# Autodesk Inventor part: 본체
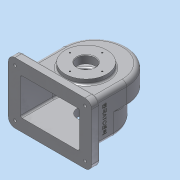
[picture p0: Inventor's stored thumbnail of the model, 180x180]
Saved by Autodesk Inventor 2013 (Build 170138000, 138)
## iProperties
Created: 2017-11
Part Number: 본체
Material: 알루미늄 6061
Document SubType Name: Modeling
Designer: dgall
Density: 2.71 g/cm^3
Mass: 1079.49 g
Surface Area: 1182.07 cm^2
Volume: 398.335 cm^3
Author: dgall
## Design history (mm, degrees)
sketch "스케치3"
  geometry: L1 (-58, 0)-(-58, -80); L2 (-58, -80)-(58, -80); L3 (58, -80)-(58, 0); A1 r 58 centre (0, 0) between (58, 0) and (-58, 0); 1 further point
  constraints: 6 end point, 2 point on circle, 2 tangent, 1 centre point, 1 coincident, 1 horizontal alignment, 1 perpendicular, 1 vertical
  dimensions: "d8" = 58 radius of A1; "d9" = 80 distance of L1.start L1.end
extrude "돌출2" new body sketch "스케치3" stored distance "d10" = 38; taper "d11" = 0 deg
sketch "스케치4"
  geometry: L1 (-58, 0)-(-58, -80) reference; L2 (-58, -80)-(58, -80) reference; L3 (58, -80)-(58, 0) reference; L4 (-58, -23)-(-58, -80); L5 (58, -80)-(-58, -80); L6 (58, -80)-(58, -23); A1 r 58 centre (0, 0) between (58, 0) and (-58, 0) reference; A2 r 58 centre (0, -23) between (58, -23) and (-58, -23)
  constraints: 6 end point, 2 collinear, 2 point on circle, 2 point on line, 1 centre point, 1 vertical alignment
  dimensions: "d12" = 58 radius of A2; "d13" = 57 distance from line of A2.centre L2
extrude "돌출3" join sketch "스케치4" distance "d14" = 38; taper "d15" = 0 deg
feature "쉘1" dims "d16" = 5
sketch "스케치5"
  geometry: L1 (5, -71)-(5, -5) reference; L2 (116, 0)-(116, -76) reference; L3 (0, 0)-(116, 0) reference; L4 (0, 0)-(0, -76) reference; L5 (116, -76)-(0, -76) reference; L6 (-17, 17)-(133, 17); L7 (133, 17)-(133, -93); L8 (133, -93)-(-17, -93); L9 (-17, -93)-(-17, 17); 4 further points
  constraints: 8 end point, 3 midpoint, 2 parallel, 1 horizontal, 1 horizontal alignment, 1 perpendicular, 1 vertical alignment
  dimensions: "d17" = 110 distance of L8.end L6.start; "d19" = 150 distance of L7.end L8.end
extrude "돌출4" join sketch "스케치5" distance "d20" = 15; taper "d21" = 0 deg
node "작업 평면3"
sketch "스케치6"
  geometry: C1 r 6 at (-75, -36); 1 further point
  constraints: 1 centre point, 1 coincident
  dimensions: "d24" = 12 diameter of C1
extrude "돌출5" join sketch "스케치6" stored distance "d25" = 15; taper "d26" = 0 deg
sketch "스케치7"
  geometry: C1 r 6 at (0, 0) reference; 1 further point
  constraints: 1 coincident
hole "구멍1" sketch "스케치7" at (0, 0) diameter "d27" = 4.459; stored, may be unused: countersink angle "d31" = 90 deg, drill point angle "d33" = 118 deg; dims "d28" = 6, "d29" = 4, "d30" = 2, "d32" = 8
sketch "스케치8"
  geometry: L1 (-75, -80)-(75, -80) reference; C1 r 37.5 at (0, -15); A1 r 58 centre (0, 0) between (58, 0) and (-58, 0) reference
  constraints: 1 centre point, 1 vertical alignment
  dimensions: "d34" = 75 diameter of C1; "d35" = 65 distance from line of C1.centre L1
extrude "돌출6" join sketch "스케치8" distance "d36" = 9; taper "d37" = 0 deg
sketch "스케치9"
  geometry: L1 (-75, -80)-(75, -80) reference; C1 r 31 at (0, -15); 1 further point
  constraints: 1 centre point, 1 vertical alignment
  dimensions: "d41" = 62 diameter of C1; "d42" = 65 distance from line of L1 C1.centre
extrude "돌출7" join sketch "스케치9" distance "d43" = 10; taper "d44" = 0 deg
sketch "스케치10"
  geometry: C1 r 31 at (0, 0) reference; 2 further points
  constraints: 1 coincident
hole "구멍2" sketch "스케치10" at (0, 0) diameter "d45" = 32; stored, may be unused: countersink angle "d49" = 90 deg, drill point angle "d51" = 118 deg; dims "d46" = 6, "d47" = 4, "d48" = 2, "d50" = 8
sketch "스케치11" dims "d52" = 52
  geometry: C1 r 31 at (0, 0) reference; 3 further points
  constraints: 2 vertical alignment, 1 coincident, 2 other
hole "구멍3" sketch "스케치11" at (0, 26) diameter "d53" = 2.459; stored, may be unused: countersink angle "d57" = 90 deg, drill point angle "d59" = 118 deg; dims "d54" = 6, "d55" = 4, "d56" = 2, "d58" = 8
sketch "스케치12" dims "d63" = 58
  geometry: C1 r 37.5 at (0, 0) reference; 3 further points
  constraints: 2 vertical alignment, 1 coincident, 2 other
hole "구멍4" sketch "스케치12" at (0, 29) diameter "d64" = 2.459; stored, may be unused: countersink angle "d68" = 90 deg, drill point angle "d70" = 118 deg; dims "d65" = 6, "d66" = 4, "d67" = 2, "d69" = 8
fillet "모깎기1" dims "d74" = 12
sketch "스케치13"
  geometry: A1 r 12 centre (-5, 81) between (-5, 93) and (-17, 81) reference; A2 r 12 centre (-5, -5) between (-17, -5) and (-5, -17) reference; A3 r 12 centre (121, -5) between (121, -17) and (133, -5) reference; A4 r 12 centre (121, 81) between (133, 81) and (121, 93) reference; 5 further points
  constraints: 4 coincident
hole "구멍5" sketch "스케치13" at (-5, -5), (-5, 81), (121, 81), (121, -5) diameter "d75" = 5; stored, may be unused: countersink angle "d79" = 90 deg, drill point angle "d81" = 118 deg; dims "d76" = 6, "d77" = 12, "d78" = 5, "d80" = 8
chamfer "모따기1" distance "d82" = 1; stored, may be unused: second distance "d83" = 2, angle "d84" = 45 deg
chamfer "모따기2" distance "d85" = 1; stored, may be unused: second distance "d86" = 2, angle "d87" = 45 deg
fillet "모깎기2" dims "d88" = 8
fillet "모깎기3" dims "d89" = 3
fillet "모깎기4" dims "d90" = 3
fillet "모깎기5" dims "d91" = 8
fillet "모깎기7" dims "d93" = 3
fillet "모깎기8" dims "d94" = 3
sketch "스케치14"
  geometry: L1 (-8, 65)-(-8, 0) reference; L2 (-25, -3)-(-25, -15) reference; L3 (-13, -15)-(-25, -15) reference; 2 further points
  constraints: 1 other
  dimensions: "d95" = 40 distance from line of L3 point (30, 25); "d96" = 38 distance from line of point (30, 25) L1
feature "엠보싱1" sketch "스케치14" dims "d8" = 58, "d9" = 80, "d97" = 0.5, "d98" = 0
fillet "모깎기9" dims "d99" = 3
node "솔리드2"
pattern_circular "원형 패턴1" dims angle "d61" = 360 deg
pattern_circular "원형 패턴2" dims angle "d72" = 360 deg
other parameters: "d22" = -144
